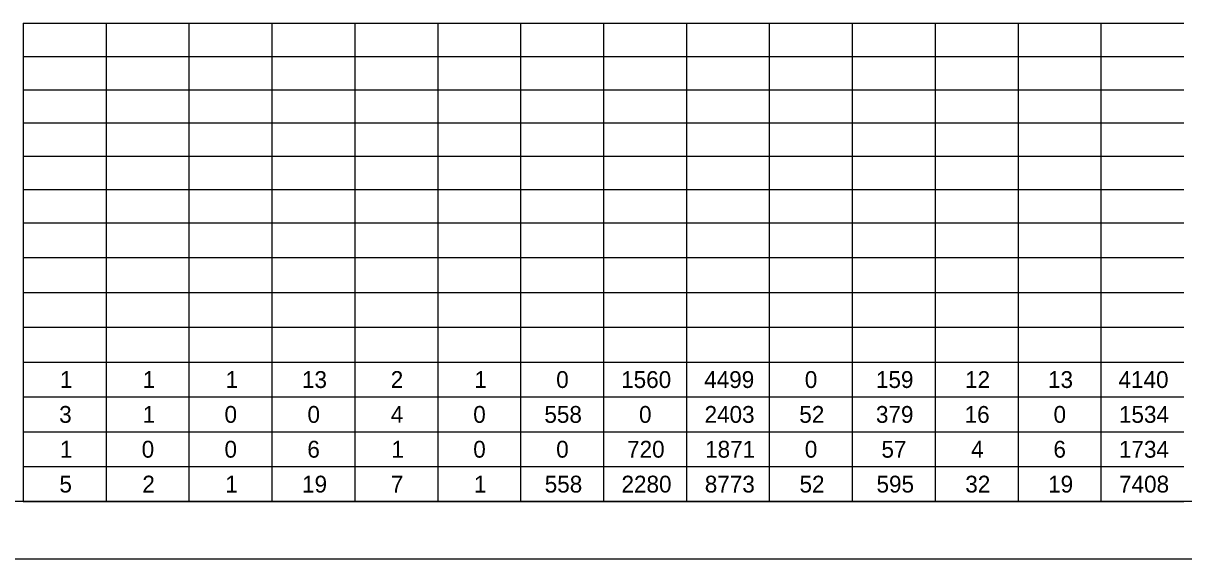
# Model space of a CAD drawing. Extents: x 0 to 34, y 0 to 22.
# Drawn here: x 13.2 to 23.33, y 0 to 4.67 of the extents above; entities that cross this region are included whole.
import ezdxf

# ---------------------------------------------------------------- set-up
doc = ezdxf.new("R2010")
doc.units = 0
for name, color, linetype in [('Default', 7, 'Continuous'), ('SH_Border', 7, 'Continuous'), ('SH_Cut_Line', 7, 'Continuous')]:
    doc.layers.add(name, color=color, linetype=linetype)

msp = doc.modelspace()

# ---------------------------------------------------------------- linework, layer by layer
at = {"layer": 'Default'}
for p, q in [((13.2, 4.672), (13.924, 4.672)), ((13.2, 4.672), (13.2, 4.092)), ((13.924, 4.672), (14.647, 4.672)), ((13.924, 4.672), (13.924, 4.092)), ((14.647, 4.672), (15.371, 4.672)), ((14.647, 4.672), (14.647, 4.092)), ((15.371, 4.672), (16.818, 4.672)), ((15.371, 4.672), (15.371, 4.092)), ((16.094, 4.672), (16.094, 4.092)), ((16.818, 4.672), (23.33, 4.672)), ((16.818, 4.672), (16.818, 4.092)), ((17.541, 4.672), (17.541, 4.092)), ((18.265, 4.672), (18.265, 4.092)), ((18.989, 4.672), (18.989, 4.092)), ((19.712, 4.672), (19.712, 4.092)), ((20.436, 4.672), (20.436, 4.092)), ((21.159, 4.672), (21.159, 4.092)), ((21.883, 4.672), (21.883, 4.092)), ((22.606, 4.672), (22.606, 4.092)), ((13.2, 4.382), (13.924, 4.382)), ((13.924, 4.382), (14.647, 4.382)), ((14.647, 4.382), (15.371, 4.382)), ((15.371, 4.382), (16.818, 4.382)), ((16.818, 4.382), (23.33, 4.382)), ((13.2, 4.092), (13.924, 4.092)), ((13.2, 4.092), (13.2, 3.802)), ((13.924, 4.092), (14.647, 4.092)), ((13.924, 4.092), (13.924, 3.802)), ((14.647, 4.092), (15.371, 4.092)), ((14.647, 4.092), (14.647, 3.802)), ((15.371, 4.092), (16.818, 4.092)), ((15.371, 4.092), (15.371, 3.802)), ((16.094, 4.092), (16.094, 3.802)), ((16.818, 4.092), (23.33, 4.092)), ((16.818, 4.092), (16.818, 3.802)), ((17.541, 4.092), (17.541, 3.802)), ((18.265, 4.092), (18.265, 3.802)), ((18.989, 4.092), (18.989, 3.802)), ((19.712, 4.092), (19.712, 3.802)), ((20.436, 4.092), (20.436, 3.802)), ((21.159, 4.092), (21.159, 3.802)), ((21.883, 4.092), (21.883, 3.802)), ((22.606, 4.092), (22.606, 3.802)), ((13.2, 3.802), (13.924, 3.802)), ((13.2, 3.802), (13.2, 3.222)), ((13.924, 3.802), (14.647, 3.802)), ((13.924, 3.802), (13.924, 3.222)), ((14.647, 3.802), (15.371, 3.802)), ((14.647, 3.802), (14.647, 3.222)), ((15.371, 3.802), (16.818, 3.802)), ((15.371, 3.802), (15.371, 3.222)), ((16.094, 3.802), (16.094, 3.222)), ((16.818, 3.802), (23.33, 3.802)), ((16.818, 3.802), (16.818, 3.222)), ((17.541, 3.802), (17.541, 3.222)), ((18.265, 3.802), (18.265, 3.222)), ((18.989, 3.802), (18.989, 3.222)), ((19.712, 3.802), (19.712, 3.222)), ((20.436, 3.802), (20.436, 3.222)), ((21.159, 3.802), (21.159, 3.222)), ((21.883, 3.802), (21.883, 3.222)), ((22.606, 3.802), (22.606, 3.222)), ((13.2, 3.512), (13.924, 3.512)), ((13.924, 3.512), (14.647, 3.512)), ((14.647, 3.512), (15.371, 3.512)), ((15.371, 3.512), (16.818, 3.512)), ((16.818, 3.512), (23.33, 3.512)), ((13.2, 3.222), (13.924, 3.222)), ((13.2, 3.222), (13.2, 2.627)), ((13.924, 3.222), (14.647, 3.222)), ((13.924, 3.222), (13.924, 2.627)), ((14.647, 3.222), (15.371, 3.222)), ((14.647, 3.222), (14.647, 2.627)), ((15.371, 3.222), (16.818, 3.222)), ((15.371, 3.222), (15.371, 2.627)), ((16.094, 3.222), (16.094, 2.627)), ((16.818, 3.222), (23.33, 3.222)), ((16.818, 3.222), (16.818, 2.627)), ((17.541, 3.222), (17.541, 2.627)), ((18.265, 3.222), (18.265, 2.627)), ((18.989, 3.222), (18.989, 2.627)), ((19.712, 3.222), (19.712, 2.627)), ((20.436, 3.222), (20.436, 2.627)), ((21.159, 3.222), (21.159, 2.627)), ((21.883, 3.222), (21.883, 2.627)), ((22.606, 3.222), (22.606, 2.627)), ((13.2, 2.931), (13.924, 2.931)), ((13.924, 2.931), (14.647, 2.931)), ((14.647, 2.931), (15.371, 2.931)), ((15.371, 2.931), (16.818, 2.931)), ((16.818, 2.931), (23.33, 2.931)), ((13.2, 2.627), (13.924, 2.627)), ((13.2, 2.627), (13.2, 2.323)), ((13.924, 2.627), (14.647, 2.627)), ((13.924, 2.627), (13.924, 2.323)), ((14.647, 2.627), (15.371, 2.627)), ((14.647, 2.627), (14.647, 2.323)), ((15.371, 2.627), (16.818, 2.627)), ((15.371, 2.627), (15.371, 2.323)), ((16.094, 2.627), (16.094, 2.323)), ((16.818, 2.627), (23.33, 2.627)), ((16.818, 2.627), (16.818, 2.323)), ((17.541, 2.627), (17.541, 2.323)), ((18.265, 2.627), (18.265, 2.323)), ((18.989, 2.627), (18.989, 2.323)), ((19.712, 2.627), (19.712, 2.323)), ((20.436, 2.627), (20.436, 2.323)), ((21.159, 2.627), (21.159, 2.323)), ((21.883, 2.627), (21.883, 2.323)), ((22.606, 2.627), (22.606, 2.323)), ((13.2, 2.323), (13.924, 2.323)), ((13.2, 2.323), (13.2, 2.02)), ((13.924, 2.323), (14.647, 2.323)), ((13.924, 2.323), (13.924, 2.02)), ((14.647, 2.323), (15.371, 2.323)), ((14.647, 2.323), (14.647, 2.02)), ((15.371, 2.323), (16.818, 2.323)), ((15.371, 2.323), (15.371, 2.02)), ((16.094, 2.323), (16.094, 2.02)), ((16.818, 2.323), (23.33, 2.323)), ((16.818, 2.323), (16.818, 2.02)), ((17.541, 2.323), (17.541, 2.02)), ((18.265, 2.323), (18.265, 2.02)), ((18.989, 2.323), (18.989, 2.02)), ((19.712, 2.323), (19.712, 2.02)), ((20.436, 2.323), (20.436, 2.02)), ((21.159, 2.323), (21.159, 2.02)), ((21.883, 2.323), (21.883, 2.02)), ((22.606, 2.323), (22.606, 2.02)), ((13.2, 2.02), (13.924, 2.02)), ((13.2, 2.02), (13.2, 1.716)), ((13.924, 2.02), (14.647, 2.02)), ((13.924, 2.02), (13.924, 1.716)), ((14.647, 2.02), (15.371, 2.02)), ((14.647, 2.02), (14.647, 1.716)), ((15.371, 2.02), (16.818, 2.02)), ((15.371, 2.02), (15.371, 1.716)), ((16.094, 2.02), (16.094, 1.716)), ((16.818, 2.02), (23.33, 2.02)), ((16.818, 2.02), (16.818, 1.716)), ((17.541, 2.02), (17.541, 1.716)), ((18.265, 2.02), (18.265, 1.716)), ((18.989, 2.02), (18.989, 1.716)), ((19.712, 2.02), (19.712, 1.716)), ((20.436, 2.02), (20.436, 1.716)), ((21.159, 2.02), (21.159, 1.716)), ((21.883, 2.02), (21.883, 1.716)), ((22.606, 2.02), (22.606, 1.716)), ((13.2, 1.716), (13.924, 1.716)), ((13.2, 1.716), (13.2, 1.412)), ((13.924, 1.716), (14.647, 1.716)), ((13.924, 1.716), (13.924, 1.412)), ((14.647, 1.716), (15.371, 1.716)), ((14.647, 1.716), (14.647, 1.412)), ((15.371, 1.716), (16.818, 1.716)), ((15.371, 1.716), (15.371, 1.412)), ((16.094, 1.716), (16.094, 1.412)), ((16.818, 1.716), (23.33, 1.716)), ((16.818, 1.716), (16.818, 1.412)), ((17.541, 1.716), (17.541, 1.412)), ((18.265, 1.716), (18.265, 1.412)), ((18.989, 1.716), (18.989, 1.412)), ((19.712, 1.716), (19.712, 1.412)), ((20.436, 1.716), (20.436, 1.412)), ((21.159, 1.716), (21.159, 1.412)), ((21.883, 1.716), (21.883, 1.412)), ((22.606, 1.716), (22.606, 1.412)), ((13.2, 1.412), (13.924, 1.412)), ((13.2, 1.412), (13.2, 1.108)), ((13.924, 1.412), (14.647, 1.412)), ((13.924, 1.412), (13.924, 1.108)), ((14.647, 1.412), (15.371, 1.412)), ((14.647, 1.412), (14.647, 1.108)), ((15.371, 1.412), (16.818, 1.412)), ((15.371, 1.412), (15.371, 1.108)), ((16.094, 1.412), (16.094, 1.108)), ((16.818, 1.412), (23.33, 1.412)), ((16.818, 1.412), (16.818, 1.108)), ((17.541, 1.412), (17.541, 1.108)), ((18.265, 1.412), (18.265, 1.108)), ((18.989, 1.412), (18.989, 1.108)), ((19.712, 1.412), (19.712, 1.108)), ((20.436, 1.412), (20.436, 1.108)), ((21.159, 1.412), (21.159, 1.108)), ((21.883, 1.412), (21.883, 1.108)), ((22.606, 1.412), (22.606, 1.108)), ((13.2, 1.108), (13.924, 1.108)), ((13.2, 1.108), (13.2, 0.804)), ((13.924, 1.108), (14.647, 1.108)), ((13.924, 1.108), (13.924, 0.804)), ((14.647, 1.108), (15.371, 1.108)), ((14.647, 1.108), (14.647, 0.804)), ((15.371, 1.108), (16.818, 1.108)), ((15.371, 1.108), (15.371, 0.804)), ((16.094, 1.108), (16.094, 0.804)), ((16.818, 1.108), (23.33, 1.108)), ((16.818, 1.108), (16.818, 0.804)), ((17.541, 1.108), (17.541, 0.804)), ((18.265, 1.108), (18.265, 0.804)), ((18.989, 1.108), (18.989, 0.804)), ((19.712, 1.108), (19.712, 0.804)), ((20.436, 1.108), (20.436, 0.804)), ((21.159, 1.108), (21.159, 0.804)), ((21.883, 1.108), (21.883, 0.804)), ((22.606, 1.108), (22.606, 0.804)), ((13.2, 0.804), (13.924, 0.804)), ((13.2, 0.804), (13.2, 0.5)), ((13.924, 0.804), (14.647, 0.804)), ((13.924, 0.804), (13.924, 0.5)), ((14.647, 0.804), (15.371, 0.804)), ((14.647, 0.804), (14.647, 0.5)), ((15.371, 0.804), (16.818, 0.804)), ((15.371, 0.804), (15.371, 0.5)), ((16.094, 0.804), (16.094, 0.5)), ((16.818, 0.804), (23.33, 0.804)), ((16.818, 0.804), (16.818, 0.5)), ((17.541, 0.804), (17.541, 0.5)), ((18.265, 0.804), (18.265, 0.5)), ((18.989, 0.804), (18.989, 0.5)), ((19.712, 0.804), (19.712, 0.5)), ((20.436, 0.804), (20.436, 0.5)), ((21.159, 0.804), (21.159, 0.5)), ((21.883, 0.804), (21.883, 0.5)), ((22.606, 0.804), (22.606, 0.5)), ((13.2, 0.5), (13.924, 0.5)), ((13.924, 0.5), (14.647, 0.5)), ((14.647, 0.5), (15.371, 0.5)), ((15.371, 0.5), (16.818, 0.5)), ((16.818, 0.5), (23.33, 0.5))]:
    msp.add_line(p, q, dxfattribs=at)
at = {"layer": 'SH_Border'}
msp.add_lwpolyline([(1.5, 21.5), (33.5, 21.5), (33.5, 0.5), (1.5, 0.5)], close=True, dxfattribs=at)
at = {"layer": 'SH_Cut_Line'}
msp.add_lwpolyline([(0, 0), (34, 0), (34, 22), (0, 22)], close=True, dxfattribs=at)

# ---------------------------------------------------------------- texts
at = {"layer": 'Default'}
for s, height, p in [('1', 0.147, (13.52, 1.49)), ('1', 0.147, (14.243, 1.49)), ('1', 0.147, (14.967, 1.49)), ('13', 0.1468, (15.633, 1.49)), ('2', 0.147, (16.408, 1.49)), ('1', 0.147, (17.138, 1.49)), ('0', 0.147, (17.852, 1.49)), ('1560', 0.1468, (18.419, 1.49)), ('4499', 0.1468, (19.144, 1.49)), ('0', 0.147, (20.022, 1.49)), ('159', 0.1468, (20.643, 1.49)), ('12', 0.1468, (21.421, 1.49)), ('13', 0.1468, (22.145, 1.49)), ('4140', 0.1468, (22.76, 1.49)), ('3', 0.147, (13.514, 1.186)), ('1', 0.147, (14.243, 1.186)), ('0', 0.147, (14.957, 1.186)), ('0', 0.147, (15.681, 1.186)), ('4', 0.147, (16.408, 1.186)), ('0', 0.147, (17.128, 1.186)), ('558', 0.1468, (17.749, 1.186)), ('0', 0.147, (18.575, 1.186)), ('2403', 0.1468, (19.147, 1.186)), ('52', 0.1468, (19.974, 1.186)), ('379', 0.1468, (20.643, 1.186)), ('16', 0.1468, (21.417, 1.186)), ('0', 0.147, (22.193, 1.186)), ('1534', 0.1468, (22.764, 1.186)), ('1', 0.147, (13.52, 0.882)), ('0', 0.147, (14.234, 0.882)), ('0', 0.147, (14.957, 0.882)), ('6', 0.147, (15.68, 0.882)), ('1', 0.147, (16.414, 0.882)), ('0', 0.147, (17.128, 0.882)), ('0', 0.147, (17.852, 0.882)), ('720', 0.1468, (18.471, 0.882)), ('1871', 0.1468, (19.152, 0.882)), ('0', 0.147, (20.022, 0.882)), ('57', 0.1468, (20.691, 0.882)), ('4', 0.147, (21.473, 0.882)), ('6', 0.147, (22.192, 0.882)), ('1734', 0.1468, (22.764, 0.882)), ('5', 0.147, (13.516, 0.578)), ('2', 0.147, (14.24, 0.578)), ('1', 0.147, (14.963, 0.578)), ('19', 0.1468, (15.634, 0.578)), ('7', 0.147, (16.409, 0.578)), ('1', 0.147, (17.134, 0.578)), ('558', 0.1468, (17.752, 0.578)), ('2280', 0.1468, (18.422, 0.578)), ('8773', 0.1468, (19.149, 0.578)), ('52', 0.1468, (19.976, 0.578)), ('595', 0.1468, (20.648, 0.578)), ('32', 0.1468, (21.423, 0.578)), ('19', 0.1468, (22.146, 0.578)), ('7408', 0.1468, (22.765, 0.578))]:
    msp.add_text(s, height=height, dxfattribs=at).set_placement(p)

doc.saveas('drawing.dxf')
